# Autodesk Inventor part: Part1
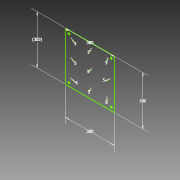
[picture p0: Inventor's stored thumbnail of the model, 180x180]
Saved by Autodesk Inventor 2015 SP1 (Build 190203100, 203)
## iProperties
Created: 2016-04
Part Number: Part1
Material: Generic
Document SubType Name: Sheet Metal
Designer: Omar
Density: 1 g/cm^3
Sheet Metal Rule: Default_mm
Appearance: Default
Author: Omar
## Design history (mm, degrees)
sketch "Sketch1"
  geometry: L1 (7.745, 7.772)-(-292.255, 7.772); L2 (-292.255, 7.772)-(-292.255, -292.228); L3 (-292.255, -292.228)-(-247.255, -292.228); L4 (7.745, -292.228)-(7.745, -247.228); L5 (-247.255, -292.228)-(-37.255, -292.228); L6 (7.745, -247.228)-(7.745, -37.228); L7 (-37.255, -292.228)-(7.745, -292.228); L8 (7.745, 4.959)-(7.745, 7.772); L9 (7.745, -37.228)-(7.745, 6.142); L10 (-274.255, -266.228)-(-270.255, -266.228); L11 (-278.255, -274.228)-(-278.255, -270.228); L12 (-266.255, -274.228)-(-266.255, -270.228); L13 (-270.255, -278.228)-(-270.255, -275.1); L14 (-270.255, -269.356)-(-270.255, -266.228); L15 (-274.255, -278.228)-(-270.255, -278.228); L16 (-278.255, -270.228)-(-275.127, -270.228); L17 (-269.382, -270.228)-(-266.255, -270.228); L18 (-274.255, -278.228)-(-274.255, -275.1); L19 (-274.255, -269.356)-(-274.255, -266.228); L20 (-278.255, -274.228)-(-275.127, -274.228); L21 (-269.382, -274.228)-(-266.255, -274.228); L22 (-266.255, -14.228)-(-266.255, -12.228); L23 (-269.382, -10.228)-(-266.255, -10.228); L24 (-278.255, -10.228)-(-275.127, -10.228); L25 (-266.255, -14.228)-(-266.255, -10.228); L26 (-278.255, -14.228)-(-278.255, -10.228); L27 (-278.255, -14.228)-(-275.127, -14.228); L28 (-274.255, -18.228)-(-270.255, -18.228); L29 (-274.255, -18.228)-(-274.255, -15.1); L30 (-270.255, -18.228)-(-270.255, -15.1); L31 (-269.382, -14.228)-(-266.255, -14.228); L32 (-270.255, -9.356)-(-270.255, -6.228); L33 (-274.255, -6.228)-(-270.255, -6.228); L34 (-274.255, -9.356)-(-274.255, -6.228); L35 (-6.255, -14.228)-(-6.255, -10.228); L36 (-9.382, -10.228)-(-6.255, -10.228); L37 (-9.382, -14.228)-(-6.255, -14.228); L38 (-14.255, -6.228)-(-10.255, -6.228); L39 (-10.255, -18.228)-(-10.255, -15.1); L40 (-10.255, -9.356)-(-10.255, -6.228); L41 (-14.255, -9.356)-(-14.255, -6.228); L42 (-14.255, -18.228)-(-10.255, -18.228); L43 (-14.255, -18.228)-(-14.255, -15.1); L44 (-18.255, -14.228)-(-18.255, -10.228); L45 (-18.255, -10.228)-(-15.127, -10.228); L46 (-18.255, -14.228)-(-15.127, -14.228); L47 (-18.255, -274.228)-(-18.255, -270.228); L48 (-18.255, -270.228)-(-15.127, -270.228); L49 (-18.255, -274.228)-(-15.127, -274.228); L50 (-14.255, -269.356)-(-14.255, -266.228); L51 (-14.255, -278.228)-(-14.255, -275.1); L52 (-6.255, -274.228)-(-6.255, -270.228); L53 (-9.382, -270.228)-(-6.255, -270.228); L54 (-9.382, -274.228)-(-6.255, -274.228); L55 (-10.255, -269.356)-(-10.255, -266.228); L56 (-10.255, -278.228)-(-10.255, -275.1); L57 (-14.255, -266.228)-(-10.255, -266.228); L58 (-14.255, -278.228)-(-10.255, -278.228); C1 r 2.5 at (-37.255, -37.228); C2 r 2.5 at (-37.255, -142.228); C3 r 2.5 at (-37.255, -247.228); C4 r 2.5 at (-142.255, -37.228); C5 r 2.5 at (-142.255, -142.228); C6 r 2.5 at (-142.255, -247.228); C7 r 2.5 at (-247.255, -37.228); C8 r 2.5 at (-247.255, -142.228); C9 r 2.5 at (-247.255, -247.228); A1 r 3.5 centre (-272.255, -272.228) between (-274.255, -269.356) and (-275.127, -270.228); A2 r 3.5 centre (-272.255, -272.228) between (-269.382, -270.228) and (-270.255, -269.356); A3 r 3.5 centre (-272.255, -272.228) between (-275.127, -274.228) and (-274.255, -275.1); A4 r 3.5 centre (-272.255, -272.228) between (-270.255, -275.1) and (-269.382, -274.228); A5 r 3.5 centre (-272.255, -12.228) between (-270.255, -15.1) and (-269.382, -14.228); A6 r 3.5 centre (-272.255, -12.228) between (-275.127, -14.228) and (-274.255, -15.1); A7 r 3.5 centre (-272.255, -12.228) between (-269.382, -10.228) and (-270.255, -9.356); A8 r 3.5 centre (-272.255, -12.228) between (-274.255, -9.356) and (-275.127, -10.228); A9 r 3.5 centre (-12.255, -12.228) between (-10.255, -15.1) and (-9.382, -14.228); A10 r 3.5 centre (-12.255, -12.228) between (-9.382, -10.228) and (-10.255, -9.356); A11 r 3.5 centre (-12.255, -12.228) between (-14.255, -9.356) and (-15.127, -10.228); A12 r 3.5 centre (-12.255, -12.228) between (-15.127, -14.228) and (-14.255, -15.1); A13 r 3.5 centre (-12.255, -272.228) between (-9.382, -270.228) and (-10.255, -269.356); A14 r 3.5 centre (-12.255, -272.228) between (-10.255, -275.1) and (-9.382, -274.228); A15 r 3.5 centre (-12.255, -272.228) between (-14.255, -269.356) and (-15.127, -270.228); A16 r 3.5 centre (-12.255, -272.228) between (-15.127, -274.228) and (-14.255, -275.1); 1 further point
  constraints: 116 end point, 32 point on circle, 25 centre point, 4 perpendicular, 1 horizontal, 1 point on line
  dimensions: "d0" = 300 distance of L1.start L1.end; "d1" = 300 distance of L1.end L2.end; "d2" = 300 distance of L2.end L4.start; "d3" = 300 distance of L4.start L1.start (derived); "d7" = 5 diameter of C1; "d8" = 5 diameter of C2; "d9" = 5 diameter of C3; "d10" = 5 diameter of C4; "d11" = 5 diameter of C5; "d12" = 5 diameter of C6; "d13" = 5 diameter of C7; "d14" = 5 diameter of C8; "d15" = 5 diameter of C9
other parameters: "Thickness" = 0.5, "BendRadius" = 0.5 (= Thickness), "BendReliefWidth" = 0.5 (= Thickness), "BendReliefDepth" = 0.25 (= 0.5 x Thickness), "CornerReliefSize" = 2 (= 4 x Thickness), "SeamGap" = 0.01, "MinimumRemnant" = 1 (= 2 x Thickness), "TransitionRadius" = 0.5 (= BendRadius), "JacobiRadiusSize" = 0.5 (= BendRadius), "GapSize" = 0.5 (= Thickness), "d4" = 45, "d22" = 7, "d23" = 7, "d24" = 2, "d25" = 2, "d26" = 2, "d27" = 2, "d28" = 6, "d29" = 6, "d30" = 6, "d31" = 6, "d32" = 6, "d33" = 3, "d34" = 3
